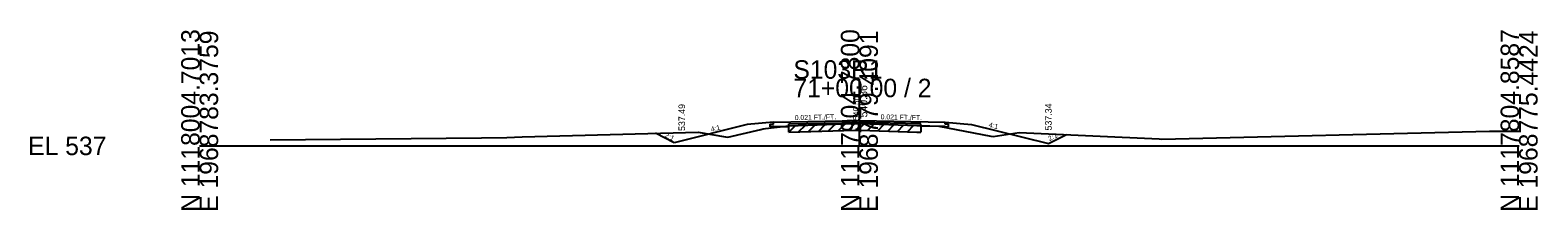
# Model space of a CAD drawing. Extents: x -26 to 203, y -10 to 12018.
# Drawn here: x -25.7 to 202.8, y 9490.3 to 9517.5 of the extents above; entities that cross this region are included whole.
import ezdxf

# ---------------------------------------------------------------- set-up
doc = ezdxf.new("R2010")
doc.units = 0
for name, color, linetype in [('Level 10', 7, 'Continuous'), ('Level 11', 7, 'Continuous'), ('Level 12', 7, 'Continuous'), ('Level 32', 7, 'Continuous'), ('Level 33', 7, 'Continuous'), ('Level 53', 7, 'Continuous'), ('Level 59', 7, 'Continuous'), ('Level 6', 7, 'Continuous'), ('Level 60', 7, 'Continuous'), ('Level 61', 7, 'Continuous'), ('Level 63', 7, 'Continuous'), ('Level 7', 7, 'Continuous')]:
    doc.layers.add(name, color=color, linetype=linetype)

msp = doc.modelspace()

# ---------------------------------------------------------------- linework, layer by layer
at = {"layer": 'Level 11'}
for p, q in [((86.5, 9503.27), (87, 9503.28)), ((86.5, 9502.91), (86.5, 9503.27)), ((87, 9502.92), (86.5, 9502.91)), ((87, 9503.28), (87, 9503.59)), ((113, 9503.28), (113, 9503.59)), ((113.5, 9503.27), (113, 9503.28)), ((113, 9502.92), (113.5, 9502.91)), ((113.5, 9502.91), (113.5, 9503.27))]:
    msp.add_line(p, q, dxfattribs=at)
at = {"layer": 'Level 12'}
for p, q in [((87, 9502.92), (89.29, 9502.96)), ((89.29, 9503.06), (89.29, 9502.96)), ((109.32, 9503.08), (109.32, 9502.99)), ((113, 9502.92), (109.32, 9502.99))]:
    msp.add_line(p, q, dxfattribs=at)
at = {"layer": 'Level 53'}
for p, q in [((89.29, 9503.32), (100, 9503.55)), ((89.29, 9503.06), (89.29, 9503.32)), ((109.32, 9503.35), (100, 9503.55)), ((109.32, 9503.08), (109.32, 9503.35))]:
    msp.add_line(p, q, dxfattribs=at)
at = {"layer": 'Level 59'}
for p, q in [((87, 9503.59), (100, 9503.86)), ((100, 9503.86), (113, 9503.59))]:
    msp.add_line(p, q, dxfattribs=at)
at = {"layer": 'Level 6'}
for p, q in [((87, 9503.59), (83, 9503.26)), ((113, 9503.59), (117, 9503.26))]:
    msp.add_line(p, q, dxfattribs=at)
at = {"layer": 'Level 60'}
for p, q in [((80.06, 9501.32), (85.04, 9502.5)), ((85.04, 9502.5), (85.42, 9502.6)), ((85.42, 9502.6), (85.75, 9502.64)), ((85.75, 9502.64), (89.29, 9503.06)), ((89.29, 9503.06), (99.31, 9503.37)), ((99.31, 9503.37), (100.18, 9503.39)), ((100.18, 9503.39), (108.69, 9503.1)), ((108.69, 9503.1), (109.32, 9503.08)), ((109.32, 9503.08), (112.02, 9502.98)), ((112.02, 9502.98), (119.92, 9501.49)), ((10.67, 9500.91), (42.71, 9501.22)), ((42.71, 9501.22), (46.54, 9501.29)), ((46.54, 9501.29), (48.9, 9501.35)), ((48.9, 9501.35), (75.55, 9502.09)), ((75.55, 9502.09), (79.7, 9501.38)), ((79.7, 9501.38), (80.06, 9501.32)), ((119.92, 9501.49), (120.29, 9501.42)), ((120.29, 9501.42), (124.23, 9502.05)), ((124.23, 9502.05), (145.46, 9501.05)), ((145.46, 9501.05), (145.84, 9501.04)), ((145.84, 9501.04), (195.53, 9502.23)), ((195.53, 9502.23), (200, 9502.22))]:
    msp.add_line(p, q, dxfattribs=at)
at = {"layer": 'Level 61'}
for p, q in [((89.29, 9502.06), (90.32, 9503.1)), ((89.29, 9502.06), (89.29, 9503.06)), ((90.79, 9502.11), (91.82, 9503.14)), ((92.29, 9502.16), (93.32, 9503.19)), ((93.79, 9502.2), (94.82, 9503.23)), ((95.29, 9502.25), (96.32, 9503.28)), ((96.79, 9502.29), (97.82, 9503.32)), ((98.29, 9502.34), (99.32, 9503.37)), ((99.31, 9502.37), (100.18, 9502.39)), ((99.79, 9502.38), (100.78, 9503.37)), ((100.18, 9502.39), (108.69, 9502.1)), ((101.29, 9502.36), (102.26, 9503.32)), ((102.79, 9502.3), (103.76, 9503.27)), ((104.29, 9502.25), (105.26, 9503.22)), ((105.79, 9502.2), (106.76, 9503.17)), ((107.29, 9502.15), (108.26, 9503.12)), ((109.32, 9503.08), (109.32, 9502.08)), ((89.29, 9502.06), (99.31, 9502.37)), ((108.69, 9502.1), (109.32, 9502.08))]:
    msp.add_line(p, q, dxfattribs=at)
at = {"layer": 'Level 63'}
for p, q in [((100, 9500), (100, 9510.18)), ((0, 9500), (100, 9500)), ((100, 9500), (200, 9500))]:
    msp.add_line(p, q, dxfattribs=at)
at = {"layer": 'Level 7'}
for p, q in [((83, 9503.26), (71.93, 9500.49)), ((117, 9503.26), (128.65, 9500.34)), ((71.93, 9500.49), (69.08, 9501.91)), ((128.65, 9500.34), (131.4, 9501.72))]:
    msp.add_line(p, q, dxfattribs=at)

# ---------------------------------------------------------------- texts
at = {"layer": 'Level 10'}
msp.add_text(' 540.50', height=0.9, rotation=90, dxfattribs=at).set_placement((99.95, 9503.54))
at = {"layer": 'Level 32'}
for s, rotation, p in [('0.021 FT./FT.', 1.1916, (90.21, 9503.91)), ('0.021 FT./FT.', 358.8084, (103.22, 9504.04)), ('4:1', 14.0362, (77.57, 9502.14)), ('4:1', 345.9638, (119.55, 9502.88)), ('2:1', 333.4349, (70.43, 9501.39)), ('2:1', 26.5651, (128.83, 9500.71))]:
    msp.add_text(s, height=0.75, rotation=rotation, dxfattribs=at).set_placement(p)
at = {"layer": 'Level 33'}
for s, p in [('537.49', (73.58, 9502.26)), ('537.34', (129.15, 9502.34))]:
    msp.add_text(s, height=1, rotation=90, dxfattribs=at).set_placement(p)
at = {"layer": 'Level 59'}
msp.add_text(' 540.86', height=1.2, rotation=90, dxfattribs=at).set_placement((101.2, 9503.86))
at = {"layer": 'Level 63'}
for s, p in [('N 1118004.7013', (0, 9490)), ('E 1968783.3759', (2.8, 9490)), ('N 1117904.7800', (100, 9490)), ('E 1968779.4091', (102.8, 9490)), ('N 1117804.8587', (200, 9490)), ('E 1968775.4424', (202.8, 9490))]:
    msp.add_text(s, height=2.8, rotation=90, dxfattribs=at).set_placement(p)
for s, p in [('S103R1', (90, 9510.18)), ('71+00.00 / 2', (90, 9507.38)), ('EL 537', (-26, 9498.6))]:
    msp.add_text(s, height=2.8, dxfattribs=at).set_placement(p)

doc.saveas('drawing.dxf')
